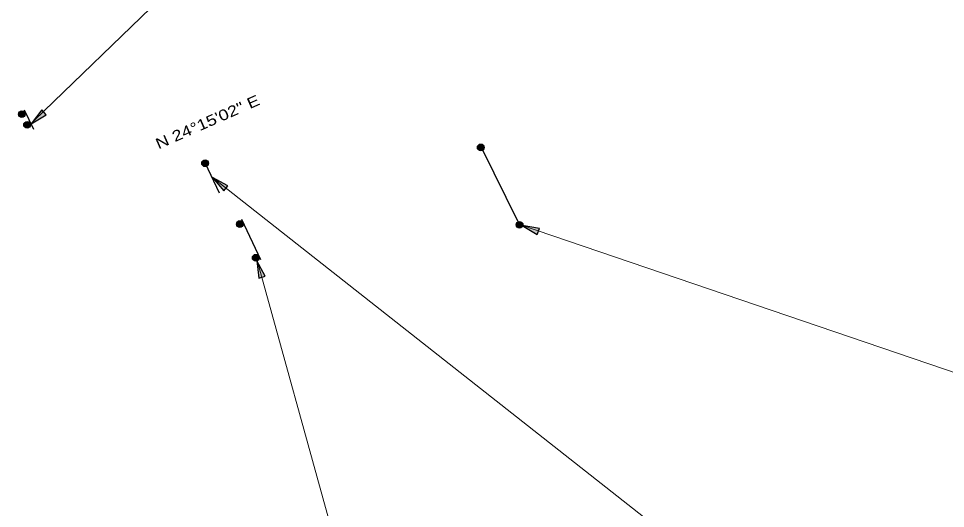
# Model space of a CAD drawing. Extents: x 2356431 to 2371438, y 6972864 to 6982525.
# Drawn here: x 2367081 to 2368116, y 6980123 to 6980671 of the extents above; entities that cross this region are included whole.
import ezdxf
from ezdxf.enums import TextEntityAlignment as Align

# ---------------------------------------------------------------- set-up
doc = ezdxf.new("R2010")
doc.units = 0
doc.header["$LTSCALE"] = 5.6
doc.layers.add('1', color=7, linetype='Continuous', lineweight=25)
doc.layers.add('28', color=7, linetype='Continuous', lineweight=35)

msp = doc.modelspace()

# ---------------------------------------------------------------- hatches: boundary and pattern name
at = {"layer": '1'}
for points in [[(2367081.195, 6980563.756, 1), (2367088.657, 6980563.621, 1)], [(2367095.159, 6980552.96), (2367111.9, 6980563.024), (2367107.121, 6980568.411)], [(2367086.996, 6980551.952, 1), (2367094.459, 6980551.817, 1)], [(2367601.125, 6980526.55, 1), (2367593.663, 6980526.674, 1)], [(2367293.217, 6980508.775, 1), (2367285.756, 6980508.976, 1)], [(2367297.678, 6980492.815), (2367310.545, 6980478.119), (2367314.997, 6980483.763)], [(2367332.113, 6980440.861, 1), (2367324.653, 6980441.095, 1)], [(2367644.577, 6980440.089, 1), (2367637.114, 6980440.213, 1)], [(2367643.858, 6980439.492), (2367660.528, 6980429.311), (2367663.091, 6980436.026)], [(2367349.848, 6980403.205, 1), (2367342.389, 6980403.439, 1)], [(2367347.386, 6980399.909), (2367349.747, 6980380.519), (2367356.604, 6980382.676)]]:
    msp.add_hatch(color=256, dxfattribs=at).paths.add_polyline_path(points)

# ---------------------------------------------------------------- linework, layer by layer
at = {"layer": '1', "lineweight": 13}
for p, q in [((2367098.802, 6980556.492), (2367372.565, 6980822.722)), ((2367297.678, 6980492.815), (2367836.822, 6980068.714)), ((2367641.836, 6980439.9), (2368132.862, 6980272.956)), ((2367347.891, 6980400.061), (2367480.094, 6979921.582))]:
    msp.add_line(p, q, dxfattribs=at)
at = {"layer": '1'}
for p, q in [((2367098.419, 6980546.45), (2367087.792, 6980568.348)), ((2367598.412, 6980526.152), (2367639.187, 6980443.228)), ((2367289.476, 6980508.879), (2367305.121, 6980475.894)), ((2367330.164, 6980446.409), (2367351.261, 6980401.413))]:
    msp.add_line(p, q, dxfattribs=at)
for points in [[(2367095.159, 6980552.96), (2367111.9, 6980563.024), (2367107.121, 6980568.411)], [(2367297.678, 6980492.815), (2367310.545, 6980478.119), (2367314.997, 6980483.763)], [(2367643.858, 6980439.492), (2367660.528, 6980429.311), (2367663.091, 6980436.026)], [(2367347.386, 6980399.909), (2367349.747, 6980380.519), (2367356.604, 6980382.676)]]:
    msp.add_lwpolyline(points, close=True, dxfattribs=at)
for centre in [(2367084.926, 6980563.689), (2367090.727, 6980551.885), (2367597.394, 6980526.612), (2367289.487, 6980508.875), (2367328.383, 6980440.978), (2367640.845, 6980440.151), (2367346.118, 6980403.322)]:
    msp.add_circle(centre, 3.732, dxfattribs=at)

# ---------------------------------------------------------------- texts
at = {"layer": '28', "width": 1.25}
msp.add_text('N 24°15\'02" E', height=12, rotation=23.813, dxfattribs=at).set_placement((2367294.658, 6980549.558), align=Align.CENTER)

doc.saveas('drawing.dxf')
